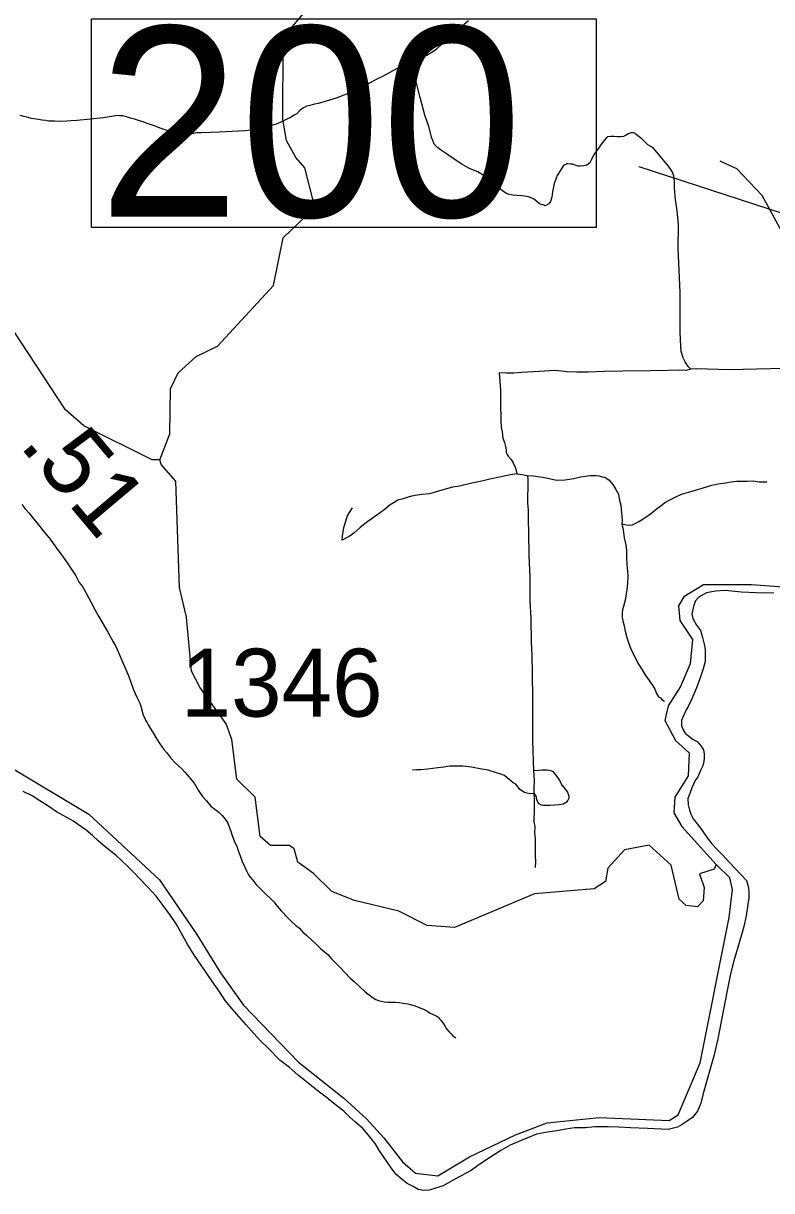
# Model space of a CAD drawing. Extents: x 2290615 to 2522933, y 819489 to 1012715.
# Drawn here: x 2306578 to 2312090, y 886266 to 894861 of the extents above; entities that cross this region are included whole.
import ezdxf

# ---------------------------------------------------------------- set-up
doc = ezdxf.new("R2010")
doc.units = 0
for name, color, linetype in [('Exist Boundary Political CountyLine', 7, 'Continuous'), ('Exist Hydrographic Misc Water Feature', 7, 'Continuous'), ('Exist Road Non-System Type 51', 7, 'Continuous'), ('Exist Road Secondary Mileage Hundredths English Label', 7, 'Continuous'), ('Exist Road Secondary Structure Standard Bridge Number Label', 7, 'Continuous'), ('Exist Road Secondary Type 20 Attributed', 7, 'Continuous'), ('Exist Road Secondary Type 51 Number Label', 7, 'Continuous')]:
    doc.layers.add(name, color=color, linetype=linetype)

msp = doc.modelspace()

# ---------------------------------------------------------------- linework, layer by layer
at = {"layer": 'Exist Boundary Political CountyLine'}
for points in [[(2312106.3, 890663.9), (2311976.4, 890666.4), (2311866.3, 890671.3), (2311748.3, 890684.1), (2311676.3, 890679.3), (2311610.6, 890666.6), (2311566.7, 890644), (2311548.9, 890629.9), (2311529.2, 890607.6), (2311515.6, 890577.5)], [(2311515.6, 890577.5), (2311502.3, 890511.5), (2311508.5, 890477.5), (2311537.1, 890429.9), (2311565.5, 890390.2), (2311580.1, 890338.4), (2311592.7, 890288.5), (2311601.1, 890250.6), (2311599.5, 890216.6), (2311599.9, 890162.5), (2311584.5, 890108.5), (2311561.3, 890034.3), (2311536, 889968), (2311500.9, 889887.6), (2311473.7, 889829.4), (2311459.9, 889805.3), (2311438.5, 889757), (2311424.7, 889726.8), (2311425.2, 889688.8), (2311437.5, 889659.1), (2311453.7, 889635.1), (2311477.9, 889615.5), (2311504.3, 889591.8), (2311542.4, 889570.1), (2311566.8, 889540.5), (2311587, 889510.7), (2311593.2, 889480.8), (2311593.6, 889452.8), (2311589.9, 889424.8), (2311582.2, 889394.7), (2311564.7, 889358.6), (2311547.1, 889312.4), (2311525.4, 889286.1), (2311502, 889231.9), (2311486.5, 889189.7), (2311472.8, 889153.5), (2311475.4, 889105.6), (2311485.7, 889067.8), (2311494.2, 889037.9), (2311512.6, 889004.1), (2311543, 888964.5), (2311577.4, 888916.7), (2311614, 888863.2), (2311648.4, 888819.6), (2311688.9, 888778), (2311729.2, 888736.4), (2311779.8, 888683.1), (2311864.8, 888591.9), (2311903.1, 888550.5), (2311919.9, 888498.6), (2311922.2, 888456.6), (2311920.7, 888420.8), (2311902, 888290.5), (2311884.9, 888210.4), (2311867.5, 888150.3), (2311838.7, 888047.8), (2311811.6, 887957.7), (2311786.8, 887861.4), (2311762, 887739.2), (2311693.9, 887384.6), (2311665.1, 887266.4), (2311586.2, 886981.6), (2311567.1, 886909.4), (2311543.7, 886851.2), (2311506.2, 886804.9), (2311466.5, 886776.4), (2311430.7, 886752), (2311395.1, 886733.7), (2311327.1, 886716.9), (2311175.2, 886723.3), (2311049.2, 886727.9), (2310965.1, 886733.1), (2310885.2, 886736.2), (2310787.2, 886735.2), (2310719.4, 886728.4), (2310637.4, 886727.4), (2310573.6, 886718.8), (2310507.7, 886706.1), (2310439.8, 886697.3), (2310358, 886680.6), (2310286.4, 886651.8), (2310228.6, 886627), (2310164.9, 886600.4), (2310095.4, 886561.8), (2309976.3, 886486.4), (2309922.6, 886447.8), (2309877.1, 886415.3), (2309797.5, 886372.7), (2309738, 886340), (2309670.3, 886301.2), (2309612.6, 886284.7), (2309566.8, 886270.2), (2309528.7, 886265.8), (2309486.8, 886273.3), (2309448.4, 886296.9), (2309406.3, 886318.4), (2309367.9, 886348), (2309323.5, 886385.4), (2309293.2, 886427.2), (2309256.6, 886480.7)], [(2309256.6, 886480.7), (2309201.7, 886560.1), (2309169.1, 886613.8), (2309120.5, 886673.2), (2309078, 886722.7), (2309025.6, 886770.2), (2308983.1, 886807.7), (2308938.7, 886851.3), (2308866.1, 886908.3), (2308809.6, 886953.8), (2308749.1, 886999.2), (2308688.7, 887048.5), (2308601.9, 887115.4), (2308537.3, 887172.8), (2308470.8, 887224), (2308379.9, 887317), (2308325.4, 887368.4), (2308276.8, 887421.8), (2308220.1, 887487.3), (2308151.3, 887564.5), (2308100.7, 887621.8), (2308064.3, 887665.6), (2308025.6, 887727), (2307966.7, 887810.4), (2307887.6, 887925.4), (2307838.8, 887996.9), (2307790, 888076.5), (2307704.2, 888229.5), (2307661.7, 888290.9), (2307608.8, 888366.4), (2307556.2, 888433.7), (2307493.5, 888503.1), (2307388.3, 888613.9), (2307343.7, 888657.5), (2307301.5, 888696.9), (2307260.9, 888734.5), (2307180.3, 888797.6), (2307129.9, 888841), (2307087.5, 888880.7), (2307041, 888920), (2306984.8, 888959.5), (2306948.5, 888987), (2306821.8, 889055.6), (2306765.4, 889095.1), (2306700.8, 889136.3), (2306644.5, 889173.6), (2306578.2, 889204.9)]]:
    msp.add_lwpolyline(points, dxfattribs=at)
at = {"layer": 'Exist Hydrographic Misc Water Feature'}
for points in [[(2307584.4, 891645.7), (2307657.4, 891839.1), (2307662.3, 892170.7), (2307719.3, 892287.9), (2307851.4, 892408.3), (2308008.2, 892483.7), (2308420.4, 892930.5), (2308491.3, 893281.3), (2308672.4, 893456.1), (2308713.4, 893556.3), (2308652.3, 893796.7), (2308585.2, 893872.7), (2308516.3, 893997.9), (2308490.3, 894154.3), (2308492.3, 894705.8), (2308533.4, 894806), (2308738.2, 895047.4)], [(2312402.3, 892890.4), (2312019.4, 893593.5), (2311834.3, 893789.4), (2311709.4, 893846.5)], [(2307584.4, 891645.7), (2307526.3, 891646.5), (2307023.4, 891898.3), (2306888.2, 892014.3), (2306397.3, 892758.9)], [(2311681.3, 888666.2), (2311665.3, 888632.8), (2311557.5, 888598.7), (2311591.3, 888498.5), (2311584.3, 888399.6), (2311543.3, 888355.3), (2311459.5, 888365), (2311409.4, 888412.1), (2311348.3, 888662.4), (2311188.4, 888810.1), (2311005.5, 888776.4), (2310882.4, 888640), (2310866.4, 888540.9), (2310783.4, 888488.3), (2310342.3, 888450.5), (2309753.4, 888203.2), (2309553.3, 888218), (2309344.3, 888324.2), (2309018.3, 888402.7), (2308851.4, 888468.1), (2308716.3, 888600.4), (2308599.4, 888684.1), (2308573.3, 888781.6), (2308539.3, 888806.5), (2308397.4, 888807.2), (2308322.4, 888873), (2308285.2, 889163.7), (2308151.3, 889296), (2308114.2, 889586.6), (2308071.4, 889702.9), (2307877.4, 889974), (2307817.3, 890089.7), (2307780.4, 890488.6), (2307727.3, 890706.3), (2307702.3, 891489.7), (2307593.2, 891613.2), (2307584.4, 891645.7)], [(2312239.4, 890704.4), (2311940.8, 890726.5), (2311586.8, 890726.5), (2311443.5, 890638.9), (2311402.4, 890571.5), (2311412.3, 890463.7), (2311505.4, 890323), (2311490.4, 890145.2), (2311417.4, 889978.1), (2311327.4, 889836.5), (2311303.4, 889727.2), (2311380.3, 889579.4), (2311481.4, 889488.4), (2311474.4, 889320.7), (2311376.4, 889162.4), (2311369.4, 889047.3), (2311428.5, 888947.9), (2311681.3, 888666.2)], [(2306492.1, 889377.8), (2307061.7, 889037.5), (2307581.6, 888553.3), (2307855.3, 888152.1), (2307941, 888011), (2308029.5, 887869.9), (2308200.9, 887632), (2308604.7, 887211.4), (2308939.2, 886945.8), (2309105.1, 886793.6), (2309232.3, 886655.3), (2309370.6, 886478.2), (2309467.4, 886395.2), (2309631.9, 886374.5), (2309863.3, 886514.1), (2310203.3, 886675.7), (2310436.5, 886764.6), (2310818.1, 886803.3), (2311335.4, 886781.3), (2311401.4, 886823.3)], [(2311401.4, 886823.3), (2311563.4, 887207.5), (2311777.5, 888276.3), (2311800.5, 888484), (2311782.4, 888568.6), (2311681.3, 888666.2)]]:
    msp.add_lwpolyline(points, dxfattribs=at)
at = {"layer": 'Exist Road Non-System Type 51'}
for points in [[(2309855.7, 894878.3), (2309742.8, 894783), (2309713.2, 894756.8), (2309685.5, 894730.4), (2309659.7, 894706.1), (2309620.1, 894671.7), (2309602.4, 894655.6), (2309550.4, 894624.8), (2309428.2, 894586.9)], [(2309428.2, 894586.9), (2309398.8, 894568.2), (2309368.9, 894548.9), (2309331.6, 894529), (2309271.9, 894495.4), (2309223.4, 894469.3), (2309176.8, 894446.9), (2309126.5, 894420.8), (2309081.7, 894392.8), (2309027.6, 894366.7), (2308982.8, 894348), (2308882.1, 894310.7), (2308807.5, 894286.4), (2308775.8, 894277.1), (2308749.7, 894271.5), (2308721.7, 894265.9), (2308688.2, 894256.6), (2308663.9, 894251), (2308641.5, 894237.9), (2308613.5, 894219.2), (2308591.7, 894194.8), (2308573.9, 894184.6), (2308546, 894166.3), (2308508.3, 894149.9), (2308474.3, 894133.5), (2308440.5, 894119.3), (2308388.8, 894102.6), (2308356.8, 894092.3), (2308329, 894086.1), (2308297.1, 894079.6), (2308255, 894075.3), (2308213.1, 894068.8), (2308067.3, 894061.2), (2308023.4, 894058.8), (2307957.4, 894058.1), (2307887.5, 894055.2), (2307855.5, 894054.9), (2307831.5, 894048.7), (2307791.6, 894042.3), (2307759.6, 894042), (2307735.6, 894045.6), (2307703.6, 894051.3), (2307679.5, 894057.1), (2307651.3, 894066.8), (2307601.2, 894084.3), (2307567.1, 894095.9), (2307543.1, 894105.5), (2307490.8, 894123), (2307460.7, 894134.8), (2307432.7, 894142.4), (2307396.6, 894156), (2307368.4, 894163.6), (2307338.4, 894173.4), (2307310.4, 894179), (2307286.3, 894180.8), (2307272.2, 894182.7), (2307228.4, 894174.3), (2307168.5, 894165.6), (2307072.7, 894154.5), (2306972.8, 894145.4), (2306926.9, 894142.9), (2306898.8, 894140.7), (2306846.9, 894138), (2306807, 894139.6), (2306766.9, 894141.3), (2306741, 894144.9), (2306716.9, 894146.7), (2306674.8, 894154.2), (2306636.7, 894159.8), (2306630.8, 894161.8), (2306604.7, 894169.5), (2306580.7, 894175.3), (2306554.5, 894182.9)], [(2309439, 894519.7), (2309432.6, 894558.1), (2309428.2, 894586.9)], [(2311494.5, 892313.2), (2311475.5, 892334), (2311451.9, 892367.2), (2311438.6, 892397.5), (2311423.4, 892443.9), (2311417.8, 892527.3), (2311416.8, 892594.6), (2311416.1, 892881.5), (2311401.2, 893203.4), (2311403.3, 893376.1), (2311392.7, 893482.6), (2311382, 893563.7), (2311373.5, 893646.8), (2311373.5, 893700.1), (2311369.2, 893738.4), (2311356.5, 893770.4), (2311328.8, 893808.8), (2311281.9, 893868.5), (2311243.5, 893913.2), (2311215.8, 893943.1), (2311177.5, 893966.5), (2311149.8, 893994.2), (2311132.8, 894011.3), (2311105.1, 894032.6), (2311090.1, 894045.4), (2311081.6, 894051.8), (2311071, 894053.9), (2311062.4, 894053.9), (2311053.9, 894053.9), (2311032.6, 894047.5), (2311013.4, 894034.8), (2310998.5, 894028.4), (2310975.1, 894026.2), (2310951.7, 894026.2), (2310930.4, 894028.4), (2310904.8, 894028.4), (2310883.5, 894024.1), (2310870.7, 894015.6), (2310843, 893983.6), (2310815.3, 893941), (2310781.2, 893896.2), (2310768.4, 893870.6), (2310759.9, 893853.6), (2310749.3, 893834.4), (2310740.7, 893825.8), (2310728, 893817.3), (2310719.4, 893813.1), (2310704.5, 893810.9), (2310679, 893808.8), (2310664, 893808.8), (2310642.7, 893815.2), (2310623.6, 893823.7), (2310608.7, 893823.7), (2310587.3, 893825.8), (2310581, 893825.8), (2310555.4, 893813.1), (2310551.1, 893806.7), (2310532, 893774.7), (2310510.6, 893740.6), (2310487.2, 893680.9), (2310476.6, 893621.2), (2310470.2, 893580.7), (2310461.6, 893548.7), (2310448.9, 893531.7), (2310431.8, 893521), (2310419, 893516.8), (2310410.5, 893521), (2310380.7, 893531.7), (2310359.4, 893548.7), (2310335.9, 893567.9), (2310318.9, 893576.4), (2310297.6, 893582.8), (2310269.9, 893589.2), (2310247.4, 893591.1), (2310215, 893594.2), (2310182.5, 893595.8), (2310157, 893599.9), (2310137.8, 893608.4), (2310116.5, 893621.2), (2310095.2, 893636.1), (2310056.9, 893663.8), (2310016.4, 893697.9), (2309971.6, 893738.4), (2309924.8, 893766.2), (2309869.4, 893789.6), (2309809.7, 893821.6), (2309747.9, 893862.1), (2309688.3, 893904.7), (2309649.9, 893930.3), (2309630.8, 893943.1), (2309615.8, 893958), (2309605.2, 893970.8), (2309598.8, 893985.7), (2309586, 894015.6), (2309564.7, 894100.8), (2309534.9, 894184), (2309500.8, 894314), (2309473.1, 894420.6), (2309449.7, 894486.7), (2309439, 894519.7)], [(2311494.5, 892313.2), (2311457.6, 892303.8), (2311403.6, 892306.9), (2311327.9, 892305.4), (2311193.6, 892302.3), (2310989.9, 892299.2), (2310858.7, 892296.1), (2310738.3, 892293), (2310654.9, 892293), (2310582.3, 892294.5), (2310543.8, 892299.2), (2310489.7, 892303.8), (2310380.1, 892297.6), (2310247.4, 892289.9), (2310190.3, 892285.3), (2310137.8, 892285.3), (2310083.8, 892288.4), (2310091.5, 892160.2), (2310093, 892089.9), (2310093, 892031.2), (2310096.1, 891975.6), (2310094.6, 891935.4), (2310097.6, 891886), (2310103.8, 891852), (2310110, 891805.7), (2310122.3, 891774.8), (2310130.1, 891743.9), (2310133.1, 891720.8), (2310134.7, 891700.7), (2310142.4, 891685.2), (2310150.1, 891672.9), (2310170.2, 891648.2), (2310185.6, 891623.5), (2310199.5, 891592.6), (2310208.8, 891567.9), (2310211.6, 891543.5)], [(2313818.3, 892338.2), (2313760.1, 892335.6), (2313494.9, 892338), (2313449.8, 892338.8), (2313359.5, 892338.8), (2313316.8, 892336.4), (2312963.6, 892332.1), (2312733.5, 892332.1), (2312522.5, 892325.7), (2312263.7, 892319.3), (2312081.5, 892316.1), (2311777.9, 892309.7), (2311535.2, 892316), (2311494.5, 892313.2)], [(2310211.6, 891543.5), (2310165.9, 891535.9), (2310085.9, 891518.1), (2310014.8, 891504.1), (2309955.1, 891488.9), (2309881.5, 891474.9), (2309791.4, 891453.3), (2309739.3, 891444.4), (2309660.6, 891424.1), (2309611.1, 891408.9), (2309570.5, 891397.4), (2309513.3, 891392.3), (2309465.1, 891384.7), (2309427, 891375.8), (2309391.4, 891365.7), (2309364.8, 891358), (2309335.6, 891349.2), (2309308.9, 891332.6), (2309281, 891314.9), (2309235.3, 891279.3), (2309180.7, 891238.6), (2309115.9, 891192.9), (2309058.8, 891148.5), (2309011.8, 891107.8), (2308977.6, 891081.1), (2308925.5, 891054.5), (2308928, 891085.6), (2308938.2, 891147.8), (2308952.2, 891196.1), (2308962.3, 891229.1), (2308981.4, 891258.3), (2309003, 891293.9)], [(2310211.6, 891543.5), (2310251.3, 891539), (2310274, 891534.5), (2310288.8, 891531)], [(2310288.8, 891531), (2310334.7, 891528.3), (2310385.5, 891520.6), (2310417.3, 891515.6), (2310451.5, 891509.2), (2310504.9, 891497.8), (2310569.6, 891499), (2310600.1, 891505.4), (2310631.8, 891510.5), (2310682.6, 891520.6), (2310719.4, 891525.7), (2310752.4, 891530.8), (2310772.7, 891532.1), (2310796.9, 891530.8), (2310818.4, 891528.3), (2310841.3, 891521.9), (2310860.3, 891518.1), (2310878.1, 891506.7), (2310890.8, 891499), (2310918.7, 891464.8), (2310942.9, 891427.9), (2310961.9, 891394.9), (2310967, 891359.3), (2310978.4, 891312.3), (2310984.8, 891255.2), (2310989.8, 891203.1), (2310987.3, 891176.4)], [(2310288.8, 891531), (2310294.4, 891508.3), (2310294.4, 891476.6), (2310294.4, 891439.1), (2310291, 891382.3), (2310292.2, 891330.1), (2310295.6, 891275.6), (2310296.7, 891206.3), (2310299, 891108.7), (2310302.4, 890939.5), (2310308, 890785.1), (2310308, 890690.9), (2310309.2, 890608), (2310316, 890480.8), (2310318.3, 890306), (2310322.8, 890206), (2310325.1, 890074.3), (2310327.3, 889894.9), (2310328.5, 889731.5), (2310327.3, 889574.8), (2310336.4, 889360.2)], [(2310987.3, 891176.4), (2311020.8, 891167.4), (2311042.2, 891165.8), (2311063.5, 891168.9), (2311083.3, 891178), (2311106.2, 891190.2), (2311135.1, 891207), (2311179.3, 891236), (2311209.8, 891258.8), (2311238.7, 891283.2), (2311275.3, 891310.7), (2311301.2, 891329), (2311339.3, 891351.8), (2311374.4, 891370.1), (2311424.6, 891394.5), (2311494.7, 891414.3), (2311577, 891438.7), (2311648.6, 891460.1), (2311695.9, 891470.7), (2311750.7, 891478.4), (2311791.9, 891484.5), (2311831.5, 891490.6), (2311865, 891490.6), (2311909.2, 891490.6), (2311953.4, 891492.1), (2311997.6, 891486), (2312026.5, 891486), (2312053.9, 891486)], [(2310987.3, 891176.4), (2310994.9, 891131.5), (2311004.1, 891073.6), (2311016.3, 891020.2), (2311020.9, 890979.1), (2311020.9, 890928.8), (2311022.4, 890875.4), (2311028.5, 890828.1), (2311030, 890787), (2311028.5, 890739.7), (2311023.9, 890692.4), (2311010.2, 890613.2), (2310998, 890567.4), (2310990.4, 890541.5), (2310988, 890522.7), (2310989.2, 890507.8), (2310989.2, 890486.1), (2310993.4, 890460.7), (2311002.6, 890424.1), (2311010.2, 890384.5), (2311022.4, 890338.7), (2311034.6, 890300.6), (2311055.9, 890248.8), (2311083.3, 890192.4), (2311104.7, 890149.7), (2311135.1, 890099.4), (2311161, 890059.7), (2311188.5, 890021.6), (2311214.4, 889982), (2311229.6, 889959.1), (2311241.8, 889927.1), (2311247.9, 889913.4), (2311255.5, 889902.7), (2311270.7, 889893.6), (2311281.4, 889882.9), (2311301.2, 889870.7)], [(2307442.9, 889832), (2307461.9, 889766.4), (2307470, 889750.3), (2307480.2, 889724.5), (2307490.1, 889710.1), (2307498.8, 889696.4), (2307512.5, 889671.5), (2307529.9, 889642.9), (2307553.6, 889601.8), (2307579.7, 889562), (2307612, 889513.5), (2307635.6, 889488.6), (2307665.5, 889450), (2307695.3, 889416.4), (2307748.8, 889369.2), (2307767.4, 889346.8), (2307784.8, 889328.1), (2307812.2, 889294.5), (2307835.8, 889265.9), (2307866.9, 889213.7), (2307896.7, 889168.9), (2307926.6, 889135.3), (2307960.1, 889096.7), (2307997.4, 889066.9), (2308021.1, 889049.4), (2308043.5, 889027), (2308064.6, 889000.9), (2308080.8, 888977.3), (2308107.4, 888911.7), (2308116.8, 888881.5), (2308134.2, 888833), (2308150.4, 888803.1), (2308161.6, 888769.5), (2308174, 888731), (2308188.9, 888689.9), (2308208.8, 888647.6), (2308224, 888616.9), (2308234.2, 888596.9), (2308248.3, 888575.1), (2308266.6, 888553.4), (2308293, 888519.7), (2308315.3, 888497.8), (2308363.7, 888448.4), (2308398, 888416.8), (2308422.3, 888391.2), (2308446.6, 888359.3), (2308477, 888325.8), (2308525.5, 888274.3), (2308553.8, 888248.5), (2308586.1, 888217), (2308612.3, 888197.3), (2308636.7, 888169.4), (2308666.9, 888143.9), (2308735.6, 888080.7), (2308767.9, 888049), (2308820.4, 888003.5), (2308848.7, 887971.9), (2308909.2, 887910.5), (2308986.1, 887831.4), (2309014.4, 887805.6), (2309093.2, 887732.6), (2309147.5, 887691.2), (2309173.8, 887673.5), (2309193.8, 887665.7), (2309213.8, 887659.9), (2309236, 887656.2), (2309261.9, 887654.5), (2309291.9, 887654.7), (2309315.9, 887652.9), (2309347.8, 887651.4), (2309376.1, 887645.5), (2309410, 887641.9), (2309428.1, 887636.3), (2309454.2, 887628.5), (2309476.2, 887622.6), (2309506.2, 887609.1), (2309526.3, 887601.3), (2309550.4, 887589.5), (2309570.6, 887575.7), (2309596.7, 887563.9), (2309618.8, 887552.2), (2309633, 887542.4), (2309643.1, 887530.4), (2309653.3, 887520.6), (2309671.6, 887494.8), (2309683.8, 887474.9), (2309695.9, 887457.2), (2309712.1, 887437.2), (2309728.3, 887419.5), (2309742.4, 887405.6), (2309762.5, 887389.9)], [(2310339.1, 889189.7), (2310313.7, 889186.5), (2310287.6, 889192.1), (2310269.5, 889197.8), (2310250.2, 889209.2), (2310233.2, 889222.8), (2310221.8, 889237.6), (2310204.8, 889258), (2310186.6, 889269.3), (2310168.5, 889284.1), (2310141.2, 889305.7), (2310120.8, 889321.6), (2310095.8, 889331.8), (2310064.1, 889343.1), (2310001.7, 889361.3), (2309954, 889370.4), (2309879.1, 889384), (2309859.8, 889387.4), (2309815.6, 889390.8), (2309762.2, 889390.8), (2309718, 889392), (2309674.8, 889384), (2309631.7, 889379.5), (2309593.1, 889373.8), (2309558, 889370.4), (2309506.9, 889363.6), (2309472.9, 889363.6), (2309444.5, 889361.3)], [(2310336.4, 889360.2), (2310373.9, 889361.3), (2310396.6, 889363.6), (2310419.3, 889363.6), (2310432.9, 889364.7), (2310447.6, 889362.4), (2310461.2, 889359), (2310474.9, 889353.4), (2310486.2, 889343.1), (2310501, 889325), (2310525.9, 889286.4), (2310546.3, 889248.9), (2310569, 889221.7), (2310584.9, 889200.1), (2310591.7, 889184.2), (2310595.1, 889170.6), (2310595.1, 889161.5), (2310594, 889149), (2310591.7, 889143.3), (2310587.2, 889137.6), (2310575.9, 889122.9), (2310566.8, 889118.3), (2310553.2, 889110.4), (2310540.7, 889108.1), (2310520.2, 889107), (2310490.7, 889104.7), (2310455.6, 889102.4), (2310423.8, 889101.3), (2310406.8, 889102.4), (2310394.3, 889104.7), (2310377.3, 889114.9), (2310368.2, 889125.2), (2310364.8, 889132), (2310360.2, 889145.6), (2310358, 889155.8), (2310356.8, 889164.9), (2310353.4, 889174), (2310351.2, 889178.5), (2310346.6, 889185.3), (2310339.1, 889189.7)], [(2310336.4, 889360.2), (2310339.8, 889286.4), (2310337.6, 889228.4), (2310337.1, 889208.1), (2310339.1, 889189.7)], [(2310339.1, 889189.7), (2310340.6, 889153.9), (2310340.6, 889074.4), (2310339.1, 888983), (2310346.4, 888945.1), (2310343.1, 888900.4), (2310347.5, 888856.8), (2310347.5, 888797.5), (2310348.7, 888760.6), (2310348.7, 888729.3), (2310349.8, 888688), (2310347.5, 888644.4)]]:
    msp.add_lwpolyline(points, dxfattribs=at)
at = {"layer": 'Exist Road Secondary Structure Standard Bridge Number Label'}
msp.add_line((2314714.8, 892628.4), (2311113.9, 893804.9), dxfattribs=at)
msp.add_lwpolyline([(2307081.2, 894894), (2310797.1, 894894), (2310797.1, 893357.6), (2307081.2, 893357.6)], close=True, dxfattribs=at)
at = {"layer": 'Exist Road Secondary Type 20 Attributed'}
msp.add_lwpolyline([(2306566.8, 891318.9), (2306592.5, 891286.5), (2306620.7, 891253.3), (2306654.6, 891209.1), (2306699.2, 891155.5), (2306725.1, 891124.8), (2306751.7, 891093.3), (2306776, 891062.4), (2306793.9, 891036.9), (2306815.5, 891006.2), (2306854.5, 890953.9), (2306900, 890889.2), (2306931.5, 890843.6), (2306964.7, 890793.9), (2306989.6, 890744.8), (2307013.9, 890713.2), (2307039.3, 890670.3), (2307077.4, 890597.3), (2307106.4, 890540.1), (2307131.3, 890496.1), (2307197.6, 890383.3), (2307225.8, 890333.5), (2307240.7, 890306.2), (2307256.5, 890276.3), (2307268.1, 890249.8), (2307287.2, 890210.8), (2307354.6, 890052.2), (2307372, 890002.4), (2307388.2, 889960.1), (2307399.4, 889930.2), (2307414.3, 889899.1), (2307425.5, 889875.5), (2307435.4, 889854.4), (2307442.9, 889832)], dxfattribs=at)

# ---------------------------------------------------------------- texts
at = {"layer": 'Exist Road Secondary Mileage Hundredths English Label'}
msp.add_text('.51', height=500, rotation=310.08529, dxfattribs=at).set_placement((2306541, 891753.2))
at = {"layer": 'Exist Road Secondary Structure Standard Bridge Number Label'}
msp.add_text('200', height=1400, dxfattribs=at).set_placement((2307131.3, 893436.7))
at = {"layer": 'Exist Road Secondary Type 51 Number Label'}
msp.add_text('1346', height=500, rotation=360, dxfattribs=at).set_placement((2307736.6, 889756.1))

doc.saveas('drawing.dxf')
